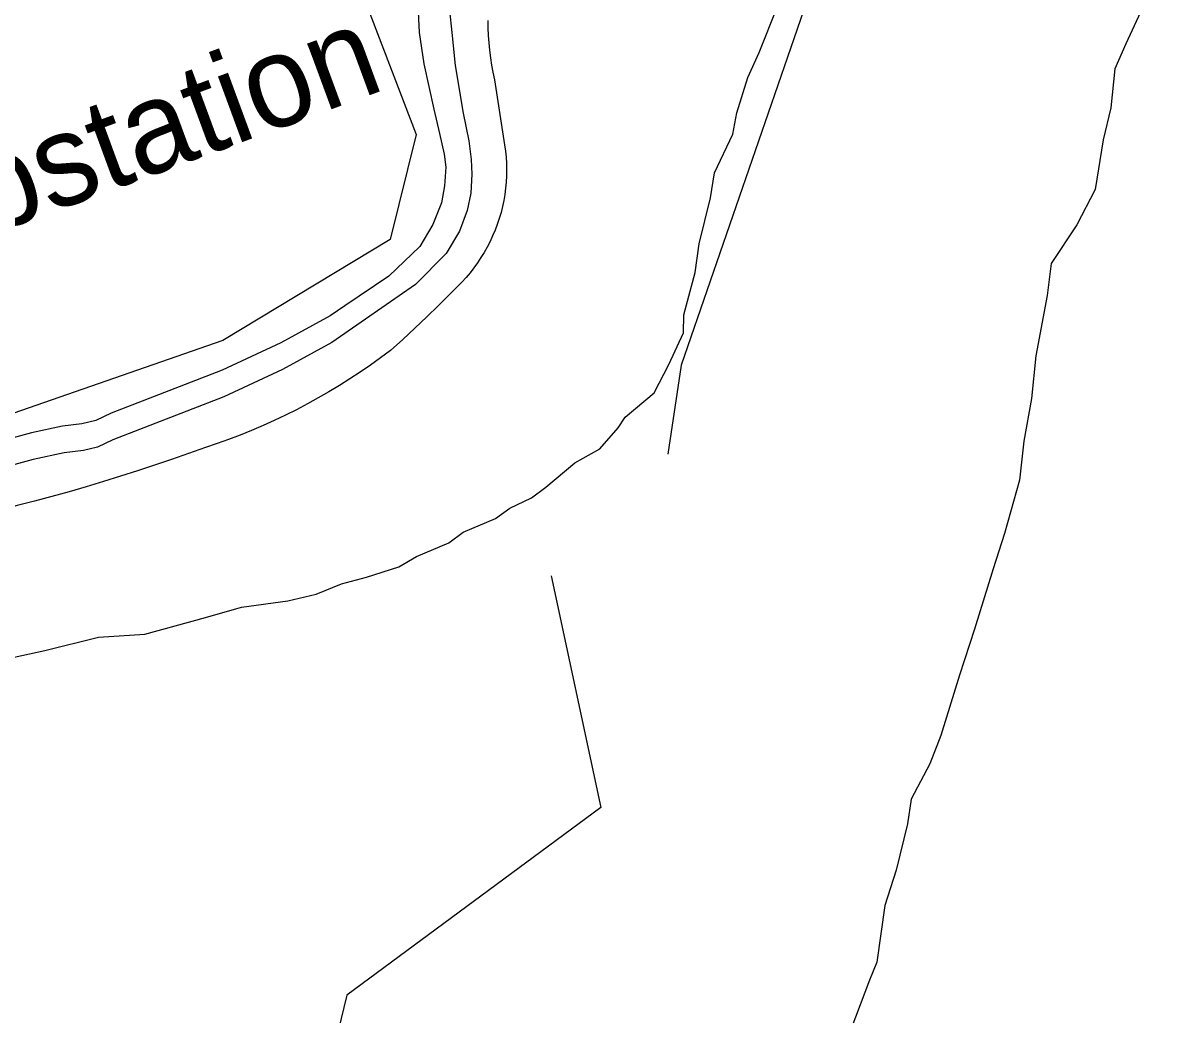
# Model space of a CAD drawing. Extents: x 3324104 to 3361979, y 612876 to 638273.
# Drawn here: x 3331707 to 3332761, y 634887 to 635790 of the extents above; entities that cross this region are included whole.
import ezdxf

# ---------------------------------------------------------------- set-up
doc = ezdxf.new("R2010")
doc.units = 0
for name, color, linetype in [('V-DTCH-CNTR', 7, 'Continuous'), ('V-SITE-OTLN', 7, 'Continuous'), ('V-SITE-OTLN-IDEN', 7, 'Continuous'), ('V-SITE-VEGE', 7, 'Continuous'), ('V-TOPO-SHOR', 7, 'Continuous')]:
    doc.layers.add(name, color=color, linetype=linetype)

msp = doc.modelspace()

# ---------------------------------------------------------------- linework, layer by layer
at = {"layer": 'V-DTCH-CNTR'}
for points in [[(3332130.3, 635792), (3332130.4, 635785.2), (3332130.6, 635778.4), (3332131.1, 635771.6), (3332131.8, 635764.9), (3332132.6, 635758.1), (3332133.7, 635751.4), (3332135, 635744.8), (3332136.4, 635738.1), (3332145.6, 635678.7), (3332146.4, 635673.1), (3332147, 635667.5), (3332147.3, 635661.9), (3332147.4, 635656.2), (3332147.3, 635650.6), (3332147, 635644.9), (3332146.5, 635639.3), (3332145.8, 635633.7), (3332144.8, 635628.2), (3332143.6, 635622.7), (3332142.3, 635617.2), (3332140.7, 635611.8), (3332138.9, 635606.4), (3332136.9, 635601.1), (3332134.7, 635595.9), (3332132.3, 635590.8), (3332129.8, 635585.8), (3332127, 635580.9), (3332124, 635576.1), (3332120.9, 635571.4), (3332117.6, 635566.8), (3332114.1, 635562.4), (3332110.5, 635558.1), (3332106.7, 635553.9), (3332096.1, 635543.3), (3332085.4, 635532.7), (3332074.7, 635522.3), (3332063.8, 635511.9), (3332052.8, 635501.7), (3332041.7, 635491.6), (3332032.7, 635484.9), (3332023.5, 635478.3), (3332014.2, 635472), (3332004.8, 635465.8), (3331995.3, 635459.8), (3331985.7, 635454), (3331975.9, 635448.4), (3331966.1, 635443), (3331956.1, 635437.7), (3331946.1, 635432.7), (3331935.9, 635427.9), (3331925.7, 635423.3), (3331915.3, 635418.8), (3331904.9, 635414.6), (3331894.4, 635410.6), (3331883.8, 635406.8), (3331873.2, 635403.2), (3331857.8, 635397.7), (3331842.5, 635392.3), (3331827, 635387.1)], [(3331827, 635387.1), (3331811.5, 635382), (3331796, 635377.1), (3331780.4, 635372.3), (3331764.8, 635367.6), (3331749.1, 635363.1), (3331733.4, 635358.8), (3331717.6, 635354.6), (3331701.9, 635350.5), (3331588.8, 635319.3), (3331422.2, 635264.5), (3331252.7, 635201.1), (3331090.2, 635147.6), (3331040.7, 635131.6), (3330937.7, 635097.4), (3330775.8, 635040.6), (3330592.2, 634980.1)]]:
    msp.add_lwpolyline(points, dxfattribs=at)
at = {"layer": 'V-SITE-OTLN'}
msp.add_lwpolyline([(3331592.3, 635400), (3331463.2, 635750.5), (3331970, 635937.5), (3331974.5, 635925.6), (3332065, 635688.2), (3332041.5, 635592.5), (3331889.2, 635500.7), (3331698, 635434.1)], close=True, dxfattribs=at)
at = {"layer": 'V-SITE-VEGE'}
for p, q in [((3332377.2, 635762.8), (3332394, 635804.6)), ((3332724.5, 635799.6), (3332711.1, 635770.6)), ((3332711.1, 635770.6), (3332701.1, 635748.1)), ((3332367.1, 635740.2), (3332377.2, 635762.8)), ((3332701.1, 635748.1), (3332697.3, 635712.5)), ((3332356.9, 635708), (3332367.1, 635740.2)), ((3332353.4, 635688.6), (3332356.9, 635708)), ((3332697.3, 635712.5), (3332690.3, 635683.4)), ((3332336.6, 635653.2), (3332353.4, 635688.6)), ((3332690.3, 635683.4), (3332683.2, 635638.2)), ((3332333, 635630.6), (3332336.6, 635653.2)), ((3332322.7, 635588.6), (3332333, 635630.6)), ((3332683.2, 635638.2), (3332666.5, 635606)), ((3332666.5, 635606), (3332643.2, 635570.7)), ((3332319, 635562.7), (3332322.7, 635588.6)), ((3332643.2, 635570.7), (3332639.5, 635541.6)), ((3332308.7, 635524), (3332319, 635562.7)), ((3332639.5, 635541.6), (3332629, 635486.7)), ((3332308.5, 635507.8), (3332308.7, 635524)), ((3332295.1, 635478.8), (3332308.5, 635507.8)), ((3332629, 635486.7), (3332625.1, 635447.8)), ((3332281.7, 635453.1), (3332295.1, 635478.8)), ((3332255.4, 635430.8), (3332281.7, 635453.1)), ((3332625.1, 635447.8), (3332618.1, 635409.1)), ((3332248.8, 635421.2), (3332255.4, 635430.8)), ((3332232.3, 635402), (3332248.8, 635421.2)), ((3332618.1, 635409.1), (3332614.3, 635373.5)), ((3332209.4, 635389.4), (3332232.3, 635402)), ((3332183.1, 635367.1), (3332209.4, 635389.4)), ((3332170, 635357.6), (3332183.1, 635367.1)), ((3332614.3, 635373.5), (3332600.6, 635325.1)), ((3332150.4, 635348.2), (3332170, 635357.6)), ((3332137.3, 635338.7), (3332150.4, 635348.2)), ((3332108, 635326.2), (3332137.3, 635338.7)), ((3332094.9, 635316.6), (3332108, 635326.2)), ((3332600.6, 635325.1), (3332590.4, 635292.8)), ((3332065.5, 635304.1), (3332094.9, 635316.6)), ((3332049.2, 635294.6), (3332065.5, 635304.1)), ((3332019.9, 635285.4), (3332049.2, 635294.6)), ((3332590.4, 635292.8), (3332573.3, 635238)), ((3331997.1, 635279.2), (3332019.9, 635285.4)), ((3331974.2, 635269.9), (3331997.1, 635279.2)), ((3331906, 635258), (3331948.2, 635263.8)), ((3331948.2, 635263.8), (3331974.2, 635269.9)), ((3331873.4, 635248.7), (3331906, 635258)), ((3331818.1, 635233.4), (3331873.4, 635248.7)), ((3331727.1, 635218.6), (3331775.9, 635230.8)), ((3331775.9, 635230.8), (3331818.1, 635233.4)), ((3332573.3, 635238), (3332559.7, 635196.1)), ((3331684.9, 635209.5), (3331727.1, 635218.6)), ((3332559.7, 635196.1), (3332542.7, 635141.2)), ((3332542.7, 635141.2), (3332532.5, 635115.5)), ((3332532.5, 635115.5), (3332515.8, 635083.3)), ((3332515.8, 635083.3), (3332512.2, 635060.7)), ((3332512.2, 635060.7), (3332501.9, 635018.7)), ((3332501.9, 635018.7), (3332491.7, 634986.5)), ((3332491.7, 634986.5), (3332484.4, 634934.7)), ((3332484.4, 634934.7), (3332477.7, 634918.6)), ((3332477.7, 634918.6), (3332460.8, 634873.5))]:
    msp.add_line(p, q, dxfattribs=at)
at = {"layer": 'V-TOPO-SHOR'}
for points in [[(3332800.3, 636016.6), (3332597.6, 635945.2), (3332567.2, 635935.1), (3332520.7, 635837.6), (3332429.5, 635835.4), (3332306.4, 635478.3), (3332294.3, 635397.1)], [(3332095.5, 635801.2), (3332097.4, 635781), (3332100.6, 635750.9), (3332108, 635707.5), (3332113.1, 635682.5), (3332115, 635665.6), (3332115.9, 635652), (3332114.9, 635634.8), (3332111.4, 635619.1), (3332104.5, 635600.1), (3332092.5, 635579.8), (3332064.5, 635551.6), (3331988.2, 635498.9), (3331943.5, 635474.3), (3331889.9, 635449.5), (3331788.9, 635410.3), (3331774.9, 635403.6), (3331762.3, 635400.5), (3331744.7, 635398.5), (3331716.4, 635392.4), (3331628.4, 635368.4)], [(3332066.6, 635806), (3332067.7, 635781.1), (3332072, 635752.4), (3332081.3, 635711.2), (3332086.4, 635689.1), (3332090.6, 635670.4), (3332092.2, 635658.6), (3332090.8, 635641.4), (3332088, 635626.1), (3332080.4, 635606.4), (3332068.4, 635586.4), (3332040.1, 635559.3), (3332000.1, 635532.4)], [(3332000.1, 635532.4), (3331986.7, 635523.1), (3331942, 635498.5), (3331888.5, 635473.7), (3331787.4, 635434.6), (3331773.4, 635427.8), (3331760.9, 635424.7), (3331743.3, 635422.8), (3331714.9, 635416.6), (3331627, 635392.7), (3331545.5, 635366.4), (3331376, 635306.3), (3331245.9, 635260.7), (3331129.4, 635219.2), (3331036.9, 635188.7), (3330923.1, 635155.3), (3330791.3, 635113.3), (3330712, 635082.3), (3330635.7, 635058.2), (3330579.7, 635040), (3330518.5, 635016.3), (3330470.2, 635001)], [(3332188.1, 635286.4), (3332233.1, 635075.6), (3332002.1, 634904.8), (3331994.1, 634872.3), (3332095.6, 634831.9), (3332132.3, 634698.1), (3332185.1, 634678), (3332193.3, 634621.2), (3332302.8, 634613.3), (3332400.3, 634548.5), (3332489.7, 634467.6), (3332530.2, 634451.4), (3332518.2, 634406.8), (3332798.2, 634326.1), (3333048.6, 634947.2), (3333088.9, 635064.9)]]:
    msp.add_lwpolyline(points, dxfattribs=at)

# ---------------------------------------------------------------- texts
at = {"layer": 'V-SITE-OTLN-IDEN'}
msp.add_text('Substation', height=83, rotation=20.2159, dxfattribs=at).set_placement((3331546.5, 635548.6))

doc.saveas('drawing.dxf')
